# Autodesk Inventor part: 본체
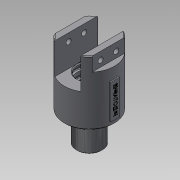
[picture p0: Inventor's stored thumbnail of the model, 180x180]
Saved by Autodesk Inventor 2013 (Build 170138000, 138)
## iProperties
Created: 2019-02
Part Number: 본체
Material: 일반
Document SubType Name: Modeling
Designer: Administrator
Density: 1 g/cm^3
Mass: 128.107 g
Surface Area: 290.427 cm^2
Volume: 128.107 cm^3
Author: Administrator
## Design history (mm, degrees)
sketch "스케치1"
  geometry: C1 r 29 at (0, 0); 1 further point
  constraints: 1 centre point, 1 coincident
  dimensions: "d0" = 58 diameter of C1
extrude "돌출1" new body sketch "스케치1" distance "d2" = 74; taper "d3" = 0 deg
sketch "스케치2"
  geometry: L1 (0, 0)-(15, 0); L2 (0, 0)-(-15, 0); L3 (-15, 0)-(-15, 24.819); L4 (-15, 0)-(-15, -24.819); L5 (15, 0)-(15, 24.819); L6 (15, 0)-(15, -24.819); A1 r 29 centre (0, 0) between (-15, 24.819) and (-15, -24.819) reference
  constraints: 12 end point, 4 equal length, 4 point on circle, 1 horizontal, 1 perpendicular
  dimensions: "d4" = 15 distance of L1.start L1.end; "d5" = 15 distance of L1.start L2.end
extrude "돌출2" cut sketch "스케치2" distance "d6" = 36; taper "d7" = 0 deg
sketch "스케치3"
  geometry: L1 (15, 24.819)-(15, -24.819) reference; L2 (0, 0)-(-22, 0); L3 (0, 0)-(22, 0); L4 (-22, 0)-(-22, 18.894); L5 (-22, 0)-(-22, -18.894); L6 (22, 0)-(22, 18.894); L7 (22, 0)-(22, -18.894); A1 r 29 centre (0, 0) between (-15, 24.819) and (-15, -24.819) reference; A2 r 29 centre (0, 0) between (15, -24.819) and (15, 24.819) reference
  constraints: 12 end point, 4 equal length, 4 point on circle, 2 perpendicular
  dimensions: "d8" = 22 distance of L2.start L2.end; "d9" = 22 distance of L2.start L3.end
extrude "돌출3" cut sketch "스케치3" distance "d10" = 16; taper "d11" = 0 deg
sketch "스케치4"
  geometry: L1 (0, 0)-(0, 37.789) reference; L2 (0, 37.789)-(16, 37.789) reference; L3 (0, 18.894)-(9, 18.894); L4 (9, 18.894)-(9, 27.894); L5 (9, 18.894)-(9, 9.894); C1 r 3 at (9, 27.894); C2 r 3 at (9, 9.894); 1 further point
  constraints: 6 end point, 2 centre point, 2 coincident, 1 collinear, 1 midpoint, 1 parallel, 1 perpendicular
  dimensions: "d12" = 9 distance of L3.start L3.end; "d14" = 9 distance of L3.end L4.end; "d15" = 9 distance of L3.end L5.end; "d16" = 6 diameter of C1; "d17" = 6 diameter of C2
extrude "돌출4" cut sketch "스케치4" stored distance "d18" = 16; taper "d19" = 0 deg
sketch "스케치5"
  geometry: C1 r 29 at (0, 0) reference; C2 r 13 at (0, 0)
  constraints: 1 centre point, 1 coincident
  dimensions: "d20" = 26 diameter of C2
extrude "돌출5" join sketch "스케치5" distance "d21" = 5; taper "d22" = 0 deg
sketch "스케치6"
  geometry: C1 r 13 at (0, 0) reference; C2 r 15 at (0, 0)
  constraints: 1 centre point, 1 coincident
  dimensions: "d23" = 30 diameter of C2
extrude "돌출6" join sketch "스케치6" distance "d24" = 29; taper "d25" = 0 deg
feature "스레드1" dims "d26" = 10, "d27" = 0
chamfer "모따기1" distance "d28" = 1; stored, may be unused: second distance "d29" = 2, angle "d30" = 45 deg
sketch "스케치7"
  geometry: C1 r 14 at (0, 0) reference
hole "구멍1" sketch "스케치7" at (0, 0) diameter "d31" = 12.376; stored, may be unused: countersink angle "d35" = 90 deg, drill point angle "d37" = 118 deg; dims "d32" = 18, "d33" = 4, "d34" = 2, "d36" = 22
node "작업 평면1"
sketch "스케치8"
  geometry: L1 (-24.819, 38)-(24.819, 38) reference; L2 (0, 38)-(0, 11); L3 (0, 38)-(14, 38); L4 (14, 38)-(14, 18); L5 (14, 18)-(16, 18); L6 (16, 18)-(16, 11); L7 (16, 11)-(0, 11); L8 (14, 38)-(14, 33); L9 (0, 33)-(17, 33); L10 (17, 33)-(17, 35.35); L11 (17, 33)-(17, 30.65); L12 (0, 33)-(0, 24); L13 (0, 24)-(17, 24); L14 (17, 24)-(17, 26.35); L15 (17, 24)-(17, 21.65); L16 (17, 30.65)-(14, 30.65); L17 (17, 26.35)-(14, 26.35); L18 (17, 21.65)-(14, 21.65); L19 (17, 35.35)-(14, 35.35); 2 further points
  constraints: 36 end point, 10 perpendicular, 8 point on line, 3 parallel, 2 collinear, 2 midpoint
  dimensions: "d63" = 27 distance of L2.start L2.end; "d64" = 32 diameter of L6 L2; "d65" = 28 diameter of L4 L2; "d66" = 5 distance of L3.end L8.end; "d67" = 34 diameter of L9.end L2; "d68" = 7 distance of L5.end L6.end; "d69" = 2.35 distance of L9.end L10.end; "d70" = 2.35 distance of L9.end L11.end; "d71" = 9 distance of L9.start L12.end; "d72" = 34 diameter of L13.end L2; "d73" = 2.35 distance of L13.end L14.end; "d74" = 2.35 distance of L13.end L15.end
revolve "회전1" sketch "스케치8" stored, may be unused: angle "d75" = 90 deg
chamfer "모따기2" distance "d76" = 1; stored, may be unused: second distance "d77" = 2, angle "d78" = 45 deg
fillet "모깎기1" dims "d79" = 0.8
sketch "스케치10"
  geometry: C1 r 14 at (0, 0) reference; C2 r 4 at (0, 0)
  constraints: 1 centre point, 1 coincident
  dimensions: "d80" = 8 diameter of C2
extrude "돌출7" cut sketch "스케치10" stored distance "d81" = 29; taper "d82" = 0 deg
node "작업 평면3"
sketch "스케치12"
  geometry: L1 (0, 0)-(0, 5); L2 (0, 5)-(5, 5); L3 (5, 5)-(5, 45); L4 (5, 45)-(0, 45); L5 (0, 45)-(0, 5); L6 (-5, 5)-(-5, 45); L7 (-5, 45)-(0, 45); L8 (0, 5)-(-5, 5)
  constraints: 16 end point, 2 parallel, 2 symmetric about line, 1 horizontal, 1 perpendicular, 1 vertical
  dimensions: "d89" = 5 distance of L1.start L1.end; "d90" = 5 distance of L4.end L3.end; "d91" = 40 distance of L3.end L2.end
extrude "돌출8" join sketch "스케치12" stored distance "d92" = 29; taper "d93" = 0 deg
node "작업 평면4"
sketch "스케치13"
  geometry: L1 (5, 45)-(-5, 45) reference; L2 (-5, 45)-(-5, 5) reference; 2 further points
  constraints: 1 other
  dimensions: "d95" = 20 distance from line of point (0, 25) L1; "d96" = 5 distance from line of L2 point (0, 25)
feature "엠보싱1" sketch "스케치13" dims "d8" = 22, "d97" = 0.5, "d98" = 0
chamfer "모따기4" distance "d99" = 1; stored, may be unused: second distance "d100" = 2, angle "d101" = 45 deg
chamfer "모따기5" distance "d102" = 1; stored, may be unused: second distance "d103" = 2, angle "d104" = 45 deg
node "솔리드1"
node "투영된 루프1"
other parameters: "d38" = 0, "d94" = 42
